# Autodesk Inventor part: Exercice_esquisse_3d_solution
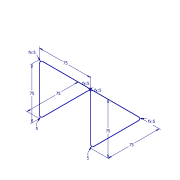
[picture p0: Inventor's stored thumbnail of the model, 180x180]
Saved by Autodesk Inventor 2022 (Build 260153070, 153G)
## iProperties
Created: 2021-06
Part Number: Exercice_esquisse_3d_solution
Material: Générique
Document SubType Name: Modeling
Designer: Fabian
Density: 1 g/cm^3
Appearance: Par défaut
Author: Fabian
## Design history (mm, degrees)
sketch "Esquisse 3D1" dims "d0" = 75, "d1" = 5, "d2" = 75, "d3" = 5 (= d1), "d4" = 75, "d5" = 5 (= d1), "d6" = 75, "d7" = 5, "d8" = 75, "d9" = 5 (= d7), "d10" = 5 (= d7)
